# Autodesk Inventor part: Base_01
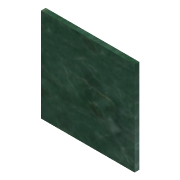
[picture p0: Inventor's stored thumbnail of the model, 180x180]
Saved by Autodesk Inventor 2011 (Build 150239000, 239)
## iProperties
Created: 2008-06
Part Number: Base_01
Document SubType Name: Modeling
Density: 1 g/cm^3
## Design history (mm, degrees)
sketch "Sketch1"
  geometry: L1 (51.422, 276.909)-(-75.578, 276.909); L2 (-75.578, 276.909)-(-75.578, 149.909); L3 (-75.578, 149.909)-(51.422, 149.909); L4 (51.422, 149.909)-(51.422, 276.909); L5 (-12.078, -137.31)-(-12.078, 23.761) reference; L6 (-12.078, 23.761)-(-12.078, 149.909)
  constraints: 12 end point, 2 parallel, 1 collinear, 1 horizontal, 1 midpoint, 1 perpendicular, 1 vertical, 2 other
  dimensions: "d0" = 127 distance of L1.end L2.end; "d1" = 127 distance of L1.start L1.end
extrude "Extrusion1" new body sketch "Sketch1" distance "d2" = 6.35; taper "d3" = 0 deg
workaxis "Work Axis1"
  workplane "Work Plane1"
  workplane "Work Plane2"
body "Solid1"
